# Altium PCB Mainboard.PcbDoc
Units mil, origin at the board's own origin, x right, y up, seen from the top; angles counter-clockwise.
Board outline 6000 x 4000 mil, 2 copper layers (Top Layer, Bottom Layer); 2 components, 233 nets, 4 pads, 0 vias.
Unrouted connection lines stored in the file: 1.
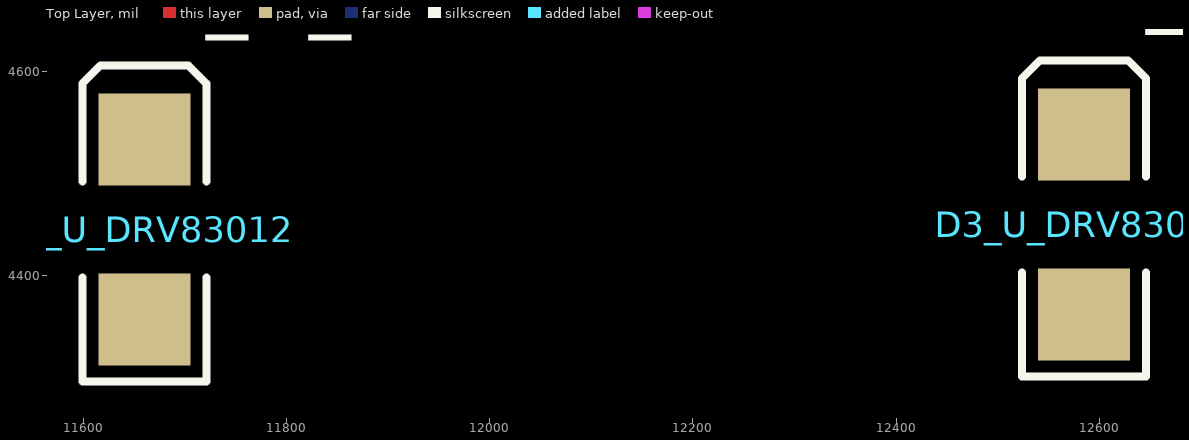
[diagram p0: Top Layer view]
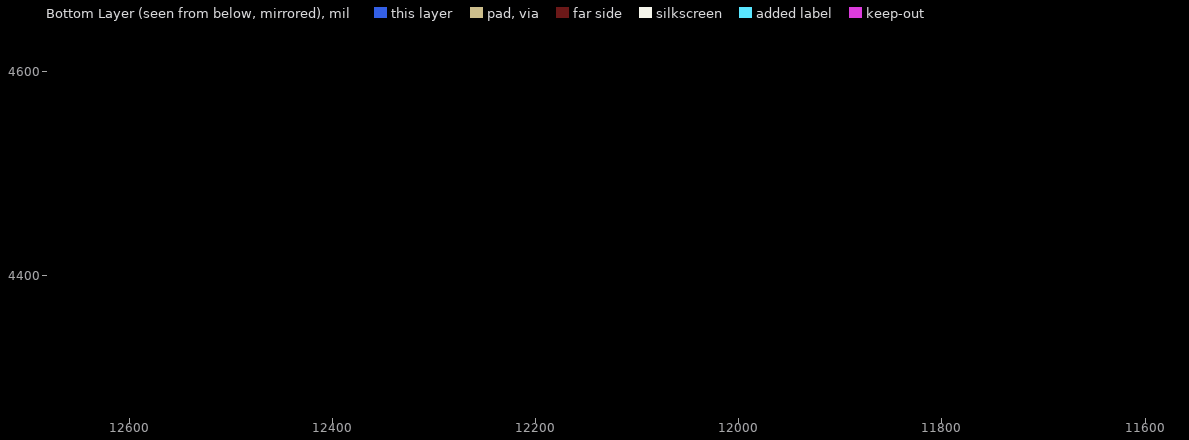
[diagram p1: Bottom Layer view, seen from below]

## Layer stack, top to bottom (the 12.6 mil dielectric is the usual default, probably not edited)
Top Solder: solder mask 0.4, Solder Resist, Dk 3.5
Top Layer: signal copper 1.4
Dielectric 1: dielectric 12.6, FR-4, Dk 4.8
Bottom Layer: signal copper 1.4
Bottom Solder: solder mask 0.4, Solder Resist, Dk 3.5

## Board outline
1000,1000 7000,1000 7000,5000 1000,5000

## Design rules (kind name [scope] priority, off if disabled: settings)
Clearance [All] p1: gap=10 ignorepadtopadclearanceinfootprint=FALSE except(0: Arc-Hole Track-Hole SMDPad-Hole THPad-Hole Via-Hole Fill-Hole Poly-Hole Region-Hole Text-Hole)
DiffPairsRouting [All] p1: maxlimit=10 minlimit=10 mostfreqgap=10 toplayer_minwidth=15 toplayer_maxwidth=15 toplayer_prefwidth=15 bottomlayer_minwidth=15 bottomlayer_maxwidth=15 bottomlayer_prefwidth=15 maxuncoupledlength=500
PolygonConnect [All] p1: connectstyle=Relief reliefconductorwidth=10 reliefentries=4 polygonreliefangle="90 Angle" airgapwidth=10
RoomDefinition U_SENSE2 [InComponentClass('U_SENSE2')] p1: confinementstyle=ConfineIn formatcopy=TRUE lockcomponents=FALSE outline 8540,4320 10540,4320 10540,5320 8540,5320
RoomDefinition U_SENSE1 [InComponentClass('U_SENSE1')] p2: confinementstyle=ConfineIn formatcopy=TRUE lockcomponents=FALSE outline 8920,2535 10920,2535 10920,3535 8920,3535
RoomDefinition U_Motorcontroller2 [InComponentClass('U_Motorcontroller2')] p3: confinementstyle=ConfineIn formatcopy=TRUE lockcomponents=FALSE outline 8135,5805 10135,5805 10135,6805 8135,6805
RoomDefinition U_Motorcontroller1 [InComponentClass('U_Motorcontroller1')] p4: confinementstyle=ConfineIn formatcopy=TRUE lockcomponents=FALSE outline 4860,6390 6860,6390 6860,7390 4860,7390
RoomDefinition U_MOTOR2 [InComponentClass('U_MOTOR2')] p5: confinementstyle=ConfineIn formatcopy=TRUE lockcomponents=FALSE outline 2260,6325 4260,6325 4260,7325 2260,7325
RoomDefinition U_MOTOR1 [InComponentClass('U_MOTOR1')] p6: confinementstyle=ConfineIn formatcopy=TRUE lockcomponents=FALSE outline 11215,6250 13215,6250 13215,7250 11215,7250
RoomDefinition U_DRV83012 [InComponentClass('U_DRV83012')] p7: confinementstyle=ConfineIn formatcopy=TRUE lockcomponents=FALSE outline 11590,4285 12375,4285 12375,4730 11590,4730
RoomDefinition U_DRV83011 [InComponentClass('U_DRV83011')] p8: confinementstyle=ConfineIn formatcopy=TRUE lockcomponents=FALSE outline 12515,4290 13280,4290 13280,4735 12515,4735
RoomDefinition Mastercontroller [InComponentClass('Mastercontroller')] p9: confinementstyle=ConfineIn formatcopy=TRUE lockcomponents=FALSE outline 11180,4955 13180,4955 13180,5955 11180,5955
RoutingVias [All] p1: holewidth=28 width=50 viastyle="Through Hole" minholewidth=28 minwidth=50 maxholewidth=28 maxwidth=50
SolderMaskExpansion [All] p1: expansion=4
Width [All] p1: maxlimit=10 minlimit=10 preferedwidth=10
29 further rules are at their usual default settings.

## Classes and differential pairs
channel class Top_Sheet: U_Top_Sheet1 U_Top_Sheet2
channel class SENSE: U_SENSE1 U_SENSE2
channel class Motorcontroller: U_Motorcontroller1 U_Motorcontroller2
channel class MOTOR: U_MOTOR1 U_MOTOR2
channel class DRV8301: U_DRV83011 U_DRV83012
differential pair C_ISENSE_U_MOTOR2: +C_ISENSE_U_MOTOR2_P -C_ISENSE_U_MOTOR2_N
differential pair C_ISENSE_U_MOTOR1: +C_ISENSE_U_MOTOR1_P -C_ISENSE_U_MOTOR1_N
differential pair B_ISENSE_U_DRV83012: +B_ISENSE_U_DRV83012_P -B_ISENSE_U_DRV83012_N
differential pair B_ISENSE_U_DRV83011: +B_ISENSE_U_DRV83011_P -B_ISENSE_U_DRV83011_N
differential pair A_ISENSE_U_DRV83012: +A_ISENSE_U_DRV83012_P -A_ISENSE_U_DRV83012_N
differential pair A_ISENSE_U_DRV83011: +A_ISENSE_U_DRV83011_P -A_ISENSE_U_DRV83011_N

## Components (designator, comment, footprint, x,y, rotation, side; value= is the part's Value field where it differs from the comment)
D3_U_DRV83011 "CDBB2100-G" SMB 12585,4450 r90 top value=100V (schematic designator D3)
D3_U_DRV83012 "CDBB2100-G" SMB 11660,4445 r90 top value=100V (schematic designator D3)

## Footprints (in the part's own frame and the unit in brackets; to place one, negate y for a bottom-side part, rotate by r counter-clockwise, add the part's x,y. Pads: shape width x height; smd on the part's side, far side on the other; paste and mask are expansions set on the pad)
SMB [mm] "DO-214-AA/SMB; 2 C-Bend Leads; Body 5.3 x 3.6 mm, inc. leads (LxW)"
  rect 2.3x2.3 smd: 1(-2.25,0) 2(2.25,0)
  silkscreen extent -3.8,-1.55 4.1,1.55

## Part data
D3_U_DRV83011 D3_U_DRV83012: library part CDBC5100-G, "Diode, Schottky, 100V, 2A, SMB", Manufacturer="Comchip Technology", Supplier Part Number 1=641-1109-1-ND, Value1=2A, Value2=0.85V

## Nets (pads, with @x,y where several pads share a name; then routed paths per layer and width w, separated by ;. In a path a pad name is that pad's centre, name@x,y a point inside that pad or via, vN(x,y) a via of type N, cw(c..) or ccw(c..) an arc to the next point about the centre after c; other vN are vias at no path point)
+3.3V: 
+3V3: 
+PVDD: 
\FAULT_U_DRV83011: 
\FAULT_U_DRV83012: 
\OCTW_U_DRV83011: 
\OCTW_U_DRV83012: 
A_ISENSE_U_DRV83011_N: 
A_ISENSE_U_DRV83011_P: 
A_ISENSE_U_DRV83012_N: 
A_ISENSE_U_DRV83012_P: 
ADCINB1_U_Motorcontroller1: 
ADCINB1_U_Motorcontroller2: 
ADCINB3_U_Motorcontroller1: 
ADCINB3_U_Motorcontroller2: 
ADCINB7_U_Motorcontroller1: 
ADCINB7_U_Motorcontroller2: 
B_ISENSE_U_DRV83011_N: 
B_ISENSE_U_DRV83011_P: 
B_ISENSE_U_DRV83012_N: 
B_ISENSE_U_DRV83012_P: 
Boot0: 
Boot1: 
C_ISENSE_U_MOTOR1_N: 
C_ISENSE_U_MOTOR1_P: 
C_ISENSE_U_MOTOR2_N: 
C_ISENSE_U_MOTOR2_P: 
DC_CAL_U_DRV83011: 
DC_CAL_U_DRV83012: 
DC_V_FB_U_Motorcontroller1: 
DC_V_FB_U_Motorcontroller2: 
DVDD: 
EN_GATE_U_DRV83011: 
EN_GATE_U_DRV83012: 
GH_A_U_DRV83011: 
GH_A_U_DRV83012: 
GH_B_U_DRV83011: 
GH_B_U_DRV83012: 
GH_C_U_DRV83011: 
GH_C_U_DRV83012: 
GL_A_U_DRV83011: 
GL_A_U_DRV83012: 
GL_B_U_DRV83011: 
GL_B_U_DRV83012: 
GL_C_U_DRV83011: 
GL_C_U_DRV83012: 
GND: D3_U_DRV83011.2 D3_U_DRV83012.2
GPIO0_U_Motorcontroller1: 
GPIO0_U_Motorcontroller2: 
GPIO1_U_Motorcontroller1: 
GPIO1_U_Motorcontroller2: 
GPIO2_U_Motorcontroller1: 
GPIO2_U_Motorcontroller2: 
GPIO3_U_Motorcontroller1: 
GPIO3_U_Motorcontroller2: 
GPIO4_U_Motorcontroller1: 
GPIO4_U_Motorcontroller2: 
GPIO5_U_Motorcontroller1: 
GPIO5_U_Motorcontroller2: 
GPIO16_U_Motorcontroller1: 
GPIO16_U_Motorcontroller2: 
GPIO17_U_Motorcontroller1: 
GPIO17_U_Motorcontroller2: 
GPIO18_U_Motorcontroller1: 
GPIO18_U_Motorcontroller2: 
GPIO19_U_Motorcontroller1: 
GPIO19_U_Motorcontroller2: 
IA_FB_U_DRV83011: 
IA_FB_U_DRV83012: 
IB_FB_U_DRV83011: 
IB_FB_U_DRV83012: 
IC_FB_U_Top_Sheet1: 
IC_FB_U_Top_Sheet2: 
LED1: 
LED2: 
LED3: 
LED4: 
NetC3_U_DRV83011_1: 
NetC3_U_DRV83011_2: 
NetC3_U_DRV83012_1: 
NetC3_U_DRV83012_2: 
NetC4_U_DRV83011_2: 
NetC4_U_DRV83012_2: 
NetC5_U_DRV83011_2: 
NetC5_U_DRV83012_2: 
NetC6_U_DRV83011_2: 
NetC6_U_DRV83012_2: 
NetC7_2: 
NetC7_U_DRV83011_2: 
NetC7_U_DRV83012_2: 
NetC8_2: 
NetC9_2: 
NetC10_2: 
NetC10_U_DRV83011_1: 
NetC10_U_DRV83012_1: 
NetC14_U_DRV83011_2: 
NetC14_U_DRV83012_2: 
NetC15_U_DRV83011_2: 
NetC15_U_DRV83012_2: 
NetC16_U_DRV83011_2: 
NetC16_U_DRV83012_2: 
NetC18_U_DRV83011_2: 
NetC18_U_DRV83012_2: 
NetC22_U_Motorcontroller1_1: 
NetC22_U_Motorcontroller2_1: 
NetC24_U_Motorcontroller1_1: 
NetC24_U_Motorcontroller2_1: 
NetC25_U_Motorcontroller1_1: 
NetC25_U_Motorcontroller2_1: 
NetC26_U_Motorcontroller1_1: 
NetC26_U_Motorcontroller2_1: 
NetC27_U_Motorcontroller1_1: 
NetC27_U_Motorcontroller2_1: 
NetC38_U_SENSE1_2: 
NetC38_U_SENSE2_2: 
NetC47_2: 
NetC49_2: 
NetIC2_U_Motorcontroller1_4: 
NetIC2_U_Motorcontroller1_6: 
NetIC2_U_Motorcontroller2_4: 
NetIC2_U_Motorcontroller2_6: 
NetIC3_U_Motorcontroller1_4: 
NetIC3_U_Motorcontroller1_6: 
NetIC3_U_Motorcontroller2_4: 
NetIC3_U_Motorcontroller2_6: 
NetIC5_U_SENSE1_2: 
NetIC5_U_SENSE1_3: 
NetIC5_U_SENSE1_5: 
NetIC5_U_SENSE2_2: 
NetIC5_U_SENSE2_3: 
NetIC5_U_SENSE2_5: 
NetJTAG_U_Motorcontroller1_13: 
NetJTAG_U_Motorcontroller1_14: 
NetJTAG_U_Motorcontroller2_13: 
NetJTAG_U_Motorcontroller2_14: 
NetLED1_1: 
NetLED1_U_Motorcontroller1_1: 
NetLED1_U_Motorcontroller2_1: 
NetLED2_1: 
NetLED2_U_Motorcontroller1_1: 
NetLED2_U_Motorcontroller2_1: 
NetLED3_1: 
NetLED3_U_Motorcontroller1_1: 
NetLED3_U_Motorcontroller2_1: 
NetLED4_1: 
NetLED4_U_Motorcontroller1_1: 
NetLED4_U_Motorcontroller2_1: 
NetQ3_U_MOTOR1_2: 
NetQ3_U_MOTOR2_2: 
NetQ4_U_MOTOR1_2: 
NetQ4_U_MOTOR2_2: 
NetQ5_U_MOTOR1_2: 
NetQ5_U_MOTOR2_2: 
NetQ6_U_MOTOR1_2: 
NetQ6_U_MOTOR2_2: 
NetQ7_U_MOTOR1_2: 
NetQ7_U_MOTOR2_2: 
NetQ8_U_MOTOR1_2: 
NetQ8_U_MOTOR2_2: 
NetR1_2: 
NetR5_2: 
NetR5_U_DRV83011_1: 
NetR5_U_DRV83012_1: 
NetR6_2: 
NetR7_U_DRV83011_2: 
NetR7_U_DRV83012_2: 
NetR10_U_DRV83011_1: 
NetR10_U_DRV83012_1: 
NetR11_U_DRV83011_1: 
NetR11_U_DRV83012_1: 
NetR15_1: 
NetR16_1: 
NRST: 
NTC1: 
NTC2: 
NTC3: 
NTC4: 
PH_U_DRV83011: D3_U_DRV83011.1
PH_U_DRV83012: D3_U_DRV83012.1
PWM_FAN1: 
PWM_FAN2: 
RESET#_U_Motorcontroller1: 
RESET#_U_Motorcontroller2: 
S_INT1: 
S_INT2: 
SH_A_U_DRV83011: 
SH_A_U_DRV83012: 
SH_B_U_DRV83011: 
SH_B_U_DRV83012: 
SH_C_U_DRV83011: 
SH_C_U_DRV83012: 
SL_A_U_DRV83011: 
SL_A_U_DRV83012: 
SL_B_U_DRV83011: 
SL_B_U_DRV83012: 
SL_C_U_DRV83011: 
SL_C_U_DRV83012: 
SPI_CS: 
SPI_MISO: 
SPI_MOSI: 
SPI_SCK: 
SWCLK: 
SWDIO: 
T1: 
T2: 
TCK_U_Motorcontroller1: 
TCK_U_Motorcontroller2: 
TDI_U_Motorcontroller1: 
TDI_U_Motorcontroller2: 
TDO_U_Motorcontroller1: 
TDO_U_Motorcontroller2: 
TMS_U_Motorcontroller1: 
TMS_U_Motorcontroller2: 
Trigger: 
TRST_U_Motorcontroller1: 
TRST_U_Motorcontroller2: 
UART_RX1: 
UART_RX2: 
UART_TX1: 
UART_TX2: 
USBCONN: 
USBDM: 
USBDP: 
VA_FB_U_Top_Sheet1: 
VA_FB_U_Top_Sheet2: 
VB_FB_U_Top_Sheet1: 
VB_FB_U_Top_Sheet2: 
VC_FB_U_Top_Sheet1: 
VC_FB_U_Top_Sheet2: 
X1_U_Motorcontroller1: 
X1_U_Motorcontroller2: 
X2_U_Motorcontroller1: 
X2_U_Motorcontroller2: 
